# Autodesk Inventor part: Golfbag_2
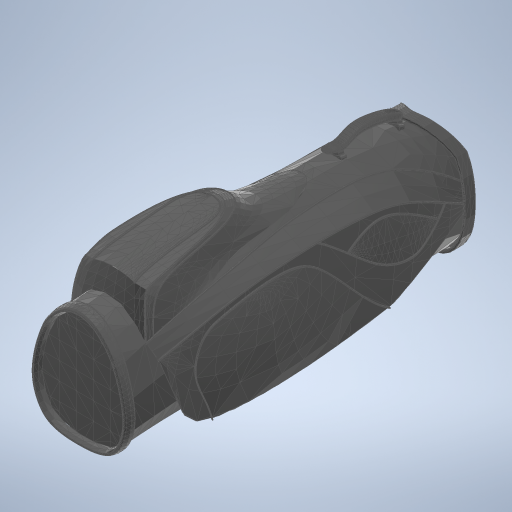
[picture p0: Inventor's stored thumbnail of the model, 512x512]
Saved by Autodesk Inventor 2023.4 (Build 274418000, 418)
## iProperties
Created: 2025-03
Part Number: Golfbag_2
Material: Générique
Document SubType Name: Modeling
Designer: bruno
Density: 1 g/cm^3
Appearance: Par défaut
Author: bruno
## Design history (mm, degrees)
node "Golfbag__2"
  node "FonctionMaillage1"
